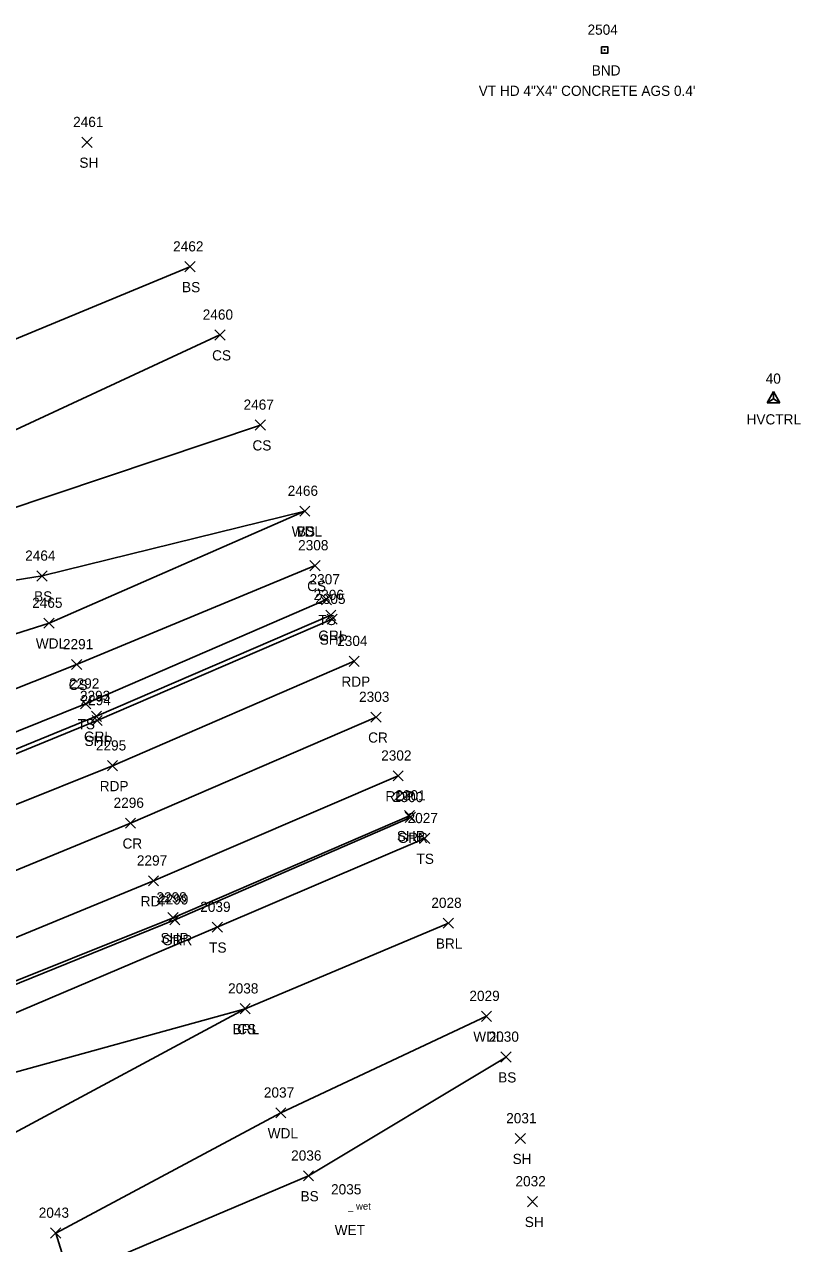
# Model space of a CAD drawing. Extents: x 1502194 to 1507887, y 142265 to 144150.
# Drawn here: x 1506842 to 1506994.3, y 143470.6 to 143709.9 of the extents above; entities that cross this region are included whole.
import ezdxf

# ---------------------------------------------------------------- set-up
doc = ezdxf.new("R2010")
doc.units = 0
for name, color, linetype in [('C_A', 7, 'Continuous'), ('C_I', 7, 'Continuous'), ('CPSM', 7, 'Continuous'), ('L_A', 7, 'Continuous'), ('L_I', 7, 'Continuous'), ('L_TIC', 7, 'Continuous'), ('LABL', 7, 'Continuous'), ('LAWA', 7, 'Continuous'), ('LELB', 7, 'Continuous'), ('LWET', 7, 'Continuous'), ('M_A', 7, 'Continuous'), ('M_C', 7, 'Continuous'), ('M_I', 7, 'Continuous'), ('MHBP', 7, 'Continuous'), ('P_A', 7, 'Continuous'), ('P_I', 7, 'Continuous'), ('P_TIC', 7, 'Continuous'), ('PET', 7, 'Continuous'), ('PRC', 7, 'Continuous'), ('PSP', 7, 'Continuous'), ('R_A', 7, 'Continuous'), ('R_I', 7, 'Continuous'), ('R_TIC', 7, 'Continuous'), ('RGR', 7, 'Continuous')]:
    doc.layers.add(name, color=color, linetype=linetype)

msp = doc.modelspace()

# ---------------------------------------------------------------- linework, layer by layer
at = {"layer": 'CPSM'}
for p, q in [((1506987.72, 143635.66), (1506988.97, 143637.83)), ((1506990.22, 143635.66), (1506988.97, 143637.83)), ((1506988.97, 143636.39), (1506988.97, 143637.83)), ((1506987.72, 143635.66), (1506988.97, 143636.39)), ((1506987.72, 143635.66), (1506990.22, 143635.66)), ((1506988.97, 143636.39), (1506988.97, 143636.39)), ((1506988.97, 143636.39), (1506990.22, 143635.66))]:
    msp.add_line(p, q, dxfattribs=at)
at = {"layer": 'L_TIC'}
for points in [[(1506853.26, 143685.76), (1506855.26, 143687.76)], [(1506855.26, 143685.76), (1506853.26, 143687.76)], [(1506873.45, 143661.34), (1506875.45, 143663.34)], [(1506875.45, 143661.34), (1506873.45, 143663.34)], [(1506879.34, 143647.95), (1506881.34, 143649.95)], [(1506881.34, 143647.95), (1506879.34, 143649.95)], [(1506887.27, 143630.28), (1506889.27, 143632.28)], [(1506889.27, 143630.28), (1506887.27, 143632.28)], [(1506895.99, 143613.38), (1506897.99, 143615.38)], [(1506897.99, 143613.38), (1506895.99, 143615.38)], [(1506895.99, 143613.38), (1506897.99, 143615.38)], [(1506897.99, 143613.38), (1506895.99, 143615.38)], [(1506898, 143602.69), (1506900, 143604.69)], [(1506900, 143602.69), (1506898, 143604.69)], [(1506844.42, 143600.65), (1506846.42, 143602.65)], [(1506846.42, 143600.65), (1506844.42, 143602.65)], [(1506900.25, 143596.01), (1506902.25, 143598.01)], [(1506902.25, 143596.01), (1506900.25, 143598.01)], [(1506845.79, 143591.4), (1506847.79, 143593.4)], [(1506847.79, 143591.4), (1506845.79, 143593.4)], [(1506851.21, 143583.27), (1506853.21, 143585.27)], [(1506853.21, 143583.27), (1506851.21, 143585.27)], [(1506852.98, 143575.57), (1506854.98, 143577.57)], [(1506854.98, 143575.57), (1506852.98, 143577.57)], [(1506919.49, 143549.15), (1506921.49, 143551.15)], [(1506921.49, 143549.15), (1506919.49, 143551.15)], [(1506878.81, 143531.73), (1506880.81, 143533.73)], [(1506880.81, 143531.73), (1506878.81, 143533.73)], [(1506924.15, 143532.52), (1506926.15, 143534.52)], [(1506926.15, 143532.52), (1506924.15, 143534.52)], [(1506884.27, 143515.72), (1506886.27, 143517.72)], [(1506886.27, 143515.72), (1506884.27, 143517.72)], [(1506884.27, 143515.72), (1506886.27, 143517.72)], [(1506886.27, 143515.72), (1506884.27, 143517.72)], [(1506931.63, 143514.25), (1506933.63, 143516.25)], [(1506933.63, 143514.25), (1506931.63, 143516.25)], [(1506935.48, 143506.25), (1506937.48, 143508.25)], [(1506937.48, 143506.25), (1506935.48, 143508.25)], [(1506891.28, 143495.29), (1506893.28, 143497.29)], [(1506893.28, 143495.29), (1506891.28, 143497.29)], [(1506938.27, 143490.25), (1506940.27, 143492.25)], [(1506940.27, 143490.25), (1506938.27, 143492.25)], [(1506896.7, 143482.93), (1506898.7, 143484.93)], [(1506898.7, 143482.93), (1506896.7, 143484.93)], [(1506940.66, 143477.88), (1506942.66, 143479.88)], [(1506942.66, 143477.88), (1506940.66, 143479.88)], [(1506847.11, 143471.7), (1506849.11, 143473.7)], [(1506849.11, 143471.7), (1506847.11, 143473.7)], [(1506847.11, 143471.7), (1506849.11, 143473.7)], [(1506849.11, 143471.7), (1506847.11, 143473.7)]]:
    msp.add_lwpolyline(points, dxfattribs=at)
at = {"layer": 'LABL'}
msp.add_lwpolyline([(1506925.15, 143533.52), (1506885.27, 143516.72), (1506839.01, 143491.82), (1506812.47, 143480.11), (1506797.79, 143478.92), (1506756.88, 143465.31), (1506714.98, 143450.06), (1506660.24, 143438.77), (1506613.3, 143423.94), (1506616.52, 143414.64)], dxfattribs=at)
at = {"layer": 'LAWA'}
for points in [[(1506522.71, 143485.76), (1506572.06, 143503.17), (1506623.68, 143515.47), (1506667.22, 143531.44), (1506692.19, 143539.75), (1506705.6, 143543.12), (1506724.44, 143544.97), (1506738.66, 143547.16), (1506749.81, 143546.64), (1506758.77, 143557.3), (1506807.57, 143579.94), (1506846.79, 143592.4), (1506896.99, 143614.38)], [(1506932.63, 143515.25), (1506892.28, 143496.29), (1506848.11, 143472.7), (1506850.82, 143464.05), (1506853.59, 143453.42), (1506870.03, 143452.38), (1506881.97, 143434.8), (1506885.44, 143414.92), (1506883.11, 143387.01), (1506858.52, 143375.25), (1506831, 143368.57)]]:
    msp.add_lwpolyline(points, dxfattribs=at)
at = {"layer": 'LELB'}
for points in [[(1506705.82, 143601.14), (1506721.55, 143616.46), (1506750.56, 143615.89), (1506769.34, 143629.36), (1506821.65, 143640.49), (1506874.45, 143662.34)], [(1506624.13, 143555.62), (1506640.38, 143556.63), (1506654.94, 143561), (1506672.72, 143565.79), (1506679.72, 143575.67), (1506695.05, 143577.62), (1506699.47, 143577.91), (1506701.5, 143575.19), (1506703.76, 143575.39), (1506707.13, 143577.97), (1506705.55, 143581.26), (1506716.61, 143587.23), (1506735.68, 143602.47), (1506756.62, 143603.39), (1506780.29, 143609.03), (1506830.83, 143625.99), (1506880.34, 143648.95)], [(1506517.85, 143501.34), (1506567.89, 143522.62), (1506612.11, 143536.7), (1506661.61, 143547.98), (1506681.76, 143559.52), (1506695.53, 143572.24), (1506704.85, 143572.91), (1506725.52, 143573.91), (1506746.5, 143587.18), (1506797.75, 143604.14), (1506837.79, 143614.31), (1506888.27, 143631.28)], [(1506520.26, 143493.12), (1506571.84, 143512.42), (1506617.89, 143527.46), (1506663.2, 143542.3), (1506684.6, 143550.02), (1506709.64, 143561.03), (1506743.74, 143569.88), (1506756.3, 143575.97), (1506802.67, 143594.79), (1506845.42, 143601.65), (1506896.99, 143614.38)], [(1506527.12, 143479.02), (1506576.48, 143493.75), (1506624.1, 143506.32), (1506671.3, 143519.58), (1506718.08, 143535.11), (1506766.47, 143551.82), (1506810.91, 143567.85), (1506852.21, 143584.27), (1506899, 143603.69)], [(1506528.28, 143476.03), (1506576.44, 143487.76), (1506625.32, 143500.66), (1506672.84, 143513.46), (1506720.65, 143528.12), (1506770.21, 143545.68), (1506814.12, 143560.53), (1506853.98, 143576.57), (1506901.25, 143597.01)], [(1506920.49, 143550.15), (1506879.81, 143532.73), (1506832.93, 143512.84), (1506791.89, 143498.35), (1506750.34, 143484.06), (1506703.75, 143467.85), (1506654.25, 143455.79), (1506605.88, 143441.31), (1506565.5, 143431.73), (1506554.53, 143418.24), (1506550.8, 143411.14), (1506553.36, 143401.15), (1506568.06, 143393.58), (1506589.98, 143377.59)], [(1506885.27, 143516.72), (1506836.36, 143503.21), (1506808.72, 143492.99), (1506794.07, 143487.49), (1506753.53, 143475.43), (1506709.32, 143458.78), (1506657.01, 143447.54), (1506608.42, 143435.74), (1506565.83, 143422.65), (1506556.41, 143414.68), (1506554.63, 143405.1), (1506570.25, 143400.38), (1506594.37, 143381.91)], [(1506936.48, 143507.25), (1506897.7, 143483.93), (1506850.82, 143464.05)]]:
    msp.add_lwpolyline(points, dxfattribs=at)
at = {"layer": 'MHBP'}
msp.add_lwpolyline([(1506955.18, 143705.5), (1506956.43, 143705.5), (1506956.43, 143704.25), (1506955.18, 143704.25)], close=True, dxfattribs=at)
msp.add_circle((1506955.8, 143704.87), 0.0833, dxfattribs=at)
at = {"layer": 'P_TIC'}
for points in [[(1506901.36, 143592.17), (1506903.36, 143594.17)], [(1506903.36, 143592.17), (1506901.36, 143594.17)], [(1506905.68, 143583.91), (1506907.68, 143585.91)], [(1506907.68, 143583.91), (1506905.68, 143585.91)], [(1506855.23, 143572.29), (1506857.23, 143574.29)], [(1506857.23, 143572.29), (1506855.23, 143574.29)], [(1506909.97, 143572.95), (1506911.97, 143574.95)], [(1506911.97, 143572.95), (1506909.97, 143574.95)], [(1506858.25, 143563.41), (1506860.25, 143565.41)], [(1506860.25, 143563.41), (1506858.25, 143565.41)], [(1506914.31, 143561.43), (1506916.31, 143563.43)], [(1506916.31, 143561.43), (1506914.31, 143563.43)], [(1506861.78, 143552.15), (1506863.78, 143554.15)], [(1506863.78, 143552.15), (1506861.78, 143554.15)], [(1506916.52, 143553.61), (1506918.52, 143555.61)], [(1506918.52, 143553.61), (1506916.52, 143555.61)], [(1506866.29, 143540.82), (1506868.29, 143542.82)], [(1506868.29, 143540.82), (1506866.29, 143542.82)], [(1506870.13, 143533.59), (1506872.13, 143535.59)], [(1506872.13, 143533.59), (1506870.13, 143535.59)]]:
    msp.add_lwpolyline(points, dxfattribs=at)
at = {"layer": 'PET'}
for points in [[(1506529.33, 143464.2), (1506579.89, 143475.85), (1506626.64, 143486.68), (1506676.46, 143499.95), (1506725.85, 143514.52), (1506772.5, 143530.8), (1506818.76, 143548.14), (1506859.25, 143564.41), (1506906.68, 143584.91)], [(1506536.88, 143441.34), (1506584.71, 143452.38), (1506632.33, 143463.25), (1506682.2, 143476.4), (1506730.21, 143490.72), (1506780.44, 143507.94), (1506828.66, 143525.9), (1506867.29, 143541.82), (1506915.31, 143562.43)]]:
    msp.add_lwpolyline(points, dxfattribs=at)
at = {"layer": 'PRC'}
msp.add_lwpolyline([(1506532.45, 143452.54), (1506582.29, 143463.86), (1506629.68, 143475.08), (1506679.65, 143488.39), (1506728.72, 143502.79), (1506776.57, 143519.3), (1506824.43, 143537.37), (1506862.78, 143553.15), (1506910.97, 143573.95)], dxfattribs=at)
at = {"layer": 'PSP'}
for points in [[(1506528.1, 143471.41), (1506577.64, 143482.92), (1506624.2, 143495.08), (1506674.01, 143508.85), (1506722.38, 143522.96), (1506769.18, 143539.06), (1506814.23, 143556.06), (1506856.23, 143573.29), (1506902.36, 143593.17)], [(1506542.57, 143434.01), (1506586.24, 143444.04), (1506633.16, 143454.96), (1506684.08, 143468.88), (1506730.5, 143482.95), (1506782.84, 143500.58), (1506831.22, 143518.57), (1506871.13, 143534.59), (1506917.52, 143554.61)]]:
    msp.add_lwpolyline(points, dxfattribs=at)
at = {"layer": 'R_TIC'}
for points in [[(1506901.1, 143592.94), (1506903.1, 143594.94)], [(1506903.1, 143592.94), (1506901.1, 143594.94)], [(1506855.11, 143573.12), (1506857.11, 143575.12)], [(1506857.11, 143573.12), (1506855.11, 143575.12)], [(1506916.7, 143553.27), (1506918.7, 143555.27)], [(1506918.7, 143553.27), (1506916.7, 143555.27)], [(1506870.47, 143533.19), (1506872.47, 143535.19)], [(1506872.47, 143533.19), (1506870.47, 143535.19)]]:
    msp.add_lwpolyline(points, dxfattribs=at)
at = {"layer": 'RGR'}
for points in [[(1506528.09, 143471.93), (1506577.33, 143484.15), (1506624.99, 143496.57), (1506673.85, 143509.85), (1506721.49, 143524.09), (1506768.89, 143540.23), (1506815.19, 143557.42), (1506856.11, 143574.12), (1506902.1, 143593.94)], [(1506543.48, 143429.76), (1506556.69, 143434.17), (1506568.66, 143438.23), (1506586.4, 143443.43), (1506633.04, 143454.6), (1506684.23, 143468.58), (1506730.71, 143482.6), (1506783.02, 143500.15), (1506831.56, 143518.03), (1506871.47, 143534.19), (1506917.7, 143554.27)]]:
    msp.add_lwpolyline(points, dxfattribs=at)

# ---------------------------------------------------------------- texts
at = {"layer": 'C_A'}
msp.add_text('HVCTRL', height=2, dxfattribs=at).set_placement((1506983.66, 143631.39))
at = {"layer": 'C_I'}
msp.add_text('40', height=2, dxfattribs=at).set_placement((1506987.42, 143639.39))
at = {"layer": 'L_A'}
for s, p in [('SH', (1506852.75, 143681.76)), ('BS', (1506872.89, 143657.34)), ('CS', (1506878.79, 143643.95)), ('CS', (1506886.71, 143626.28)), ('WDL', (1506894.41, 143609.38)), ('BS', (1506895.43, 143609.38)), ('CS', (1506897.44, 143598.69)), ('BS', (1506843.86, 143596.65)), ('TS', (1506899.66, 143592.01)), ('WDL', (1506844.2, 143587.4)), ('CS', (1506850.65, 143579.27)), ('TS', (1506852.39, 143571.57)), ('TS', (1506918.9, 143545.15)), ('BRL', (1506922.69, 143528.52)), ('TS', (1506878.21, 143527.73)), ('BRL', (1506882.81, 143511.72)), ('CS', (1506883.71, 143511.72)), ('WDL', (1506930.04, 143510.25)), ('BS', (1506934.92, 143502.25)), ('WDL', (1506889.7, 143491.29)), ('SH', (1506937.76, 143486.25)), ('BS', (1506896.14, 143478.93)), ('SH', (1506940.14, 143473.88)), ('WET', (1506902.85, 143472.29))]:
    msp.add_text(s, height=2, dxfattribs=at).set_placement(p)
at = {"layer": 'L_I'}
for s, p in [('2461', (1506851.52, 143689.76)), ('2462', (1506871.14, 143665.34)), ('2460', (1506876.95, 143651.95)), ('2467', (1506884.96, 143634.28)), ('2466', (1506893.63, 143617.38)), ('2466', (1506893.63, 143617.38)), ('2464', (1506842.11, 143604.65)), ('2308', (1506895.67, 143606.69)), ('2307', (1506897.91, 143600.01)), ('2465', (1506843.48, 143595.4)), ('2291', (1506849.52, 143587.27)), ('2292', (1506850.72, 143579.57)), ('2027', (1506917.15, 143553.15)), ('2039', (1506876.46, 143535.73)), ('2028', (1506921.81, 143536.52)), ('2038', (1506881.93, 143519.72)), ('2038', (1506881.93, 143519.72)), ('2029', (1506929.28, 143518.25)), ('2030', (1506933.05, 143510.25)), ('2037', (1506888.95, 143499.29)), ('2031', (1506936.5, 143494.25)), ('2036', (1506894.3, 143486.93)), ('2035', (1506902.13, 143480.29)), ('2032', (1506938.32, 143481.88)), ('2043', (1506844.77, 143475.7)), ('2043', (1506844.77, 143475.7))]:
    msp.add_text(s, height=2, dxfattribs=at).set_placement(p)
at = {"layer": 'LWET'}
msp.add_text('_ wet', height=1.4, dxfattribs=at).set_placement((1506905.47, 143477.29))
at = {"layer": 'M_A'}
msp.add_text('BND', height=2, dxfattribs=at).set_placement((1506953.29, 143699.87))
at = {"layer": 'M_C'}
msp.add_text('VT HD 4"X4" CONCRETE AGS 0.4\'', height=2, dxfattribs=at).set_placement((1506931.11, 143695.87))
at = {"layer": 'M_I'}
msp.add_text('2504', height=2, dxfattribs=at).set_placement((1506952.46, 143707.87))
at = {"layer": 'P_A'}
for s, p in [('SHP', (1506899.9, 143588.17)), ('RDP', (1506904.17, 143579.91)), ('CR', (1506909.41, 143568.95)), ('SHP', (1506853.76, 143568.29)), ('RDP', (1506856.74, 143559.41)), ('RDP', (1506912.8, 143557.43)), ('SHP', (1506915.05, 143549.61)), ('CR', (1506861.21, 143548.15)), ('RDP', (1506864.78, 143536.82)), ('SHP', (1506868.67, 143529.59))]:
    msp.add_text(s, height=2, dxfattribs=at).set_placement(p)
at = {"layer": 'P_I'}
for s, p in [('2305', (1506899.03, 143596.17)), ('2304', (1506903.34, 143587.91)), ('2294', (1506852.97, 143576.29)), ('2303', (1506907.63, 143576.95)), ('2295', (1506855.99, 143567.41)), ('2302', (1506911.97, 143565.43)), ('2301', (1506914.75, 143557.61)), ('2296', (1506859.46, 143556.15)), ('2297', (1506864.03, 143544.82)), ('2298', (1506867.87, 143537.59))]:
    msp.add_text(s, height=2, dxfattribs=at).set_placement(p)
at = {"layer": 'R_A'}
for s, p in [('GRL', (1506899.64, 143588.94)), ('GRL', (1506853.65, 143569.12)), ('GRR', (1506915.19, 143549.27)), ('GRR', (1506868.95, 143529.19))]:
    msp.add_text(s, height=2, dxfattribs=at).set_placement(p)
at = {"layer": 'R_I'}
for s, p in [('2306', (1506898.71, 143596.94)), ('2293', (1506852.85, 143577.12)), ('2300', (1506914.28, 143557.27)), ('2299', (1506868.2, 143537.19))]:
    msp.add_text(s, height=2, dxfattribs=at).set_placement(p)

doc.saveas('drawing.dxf')
